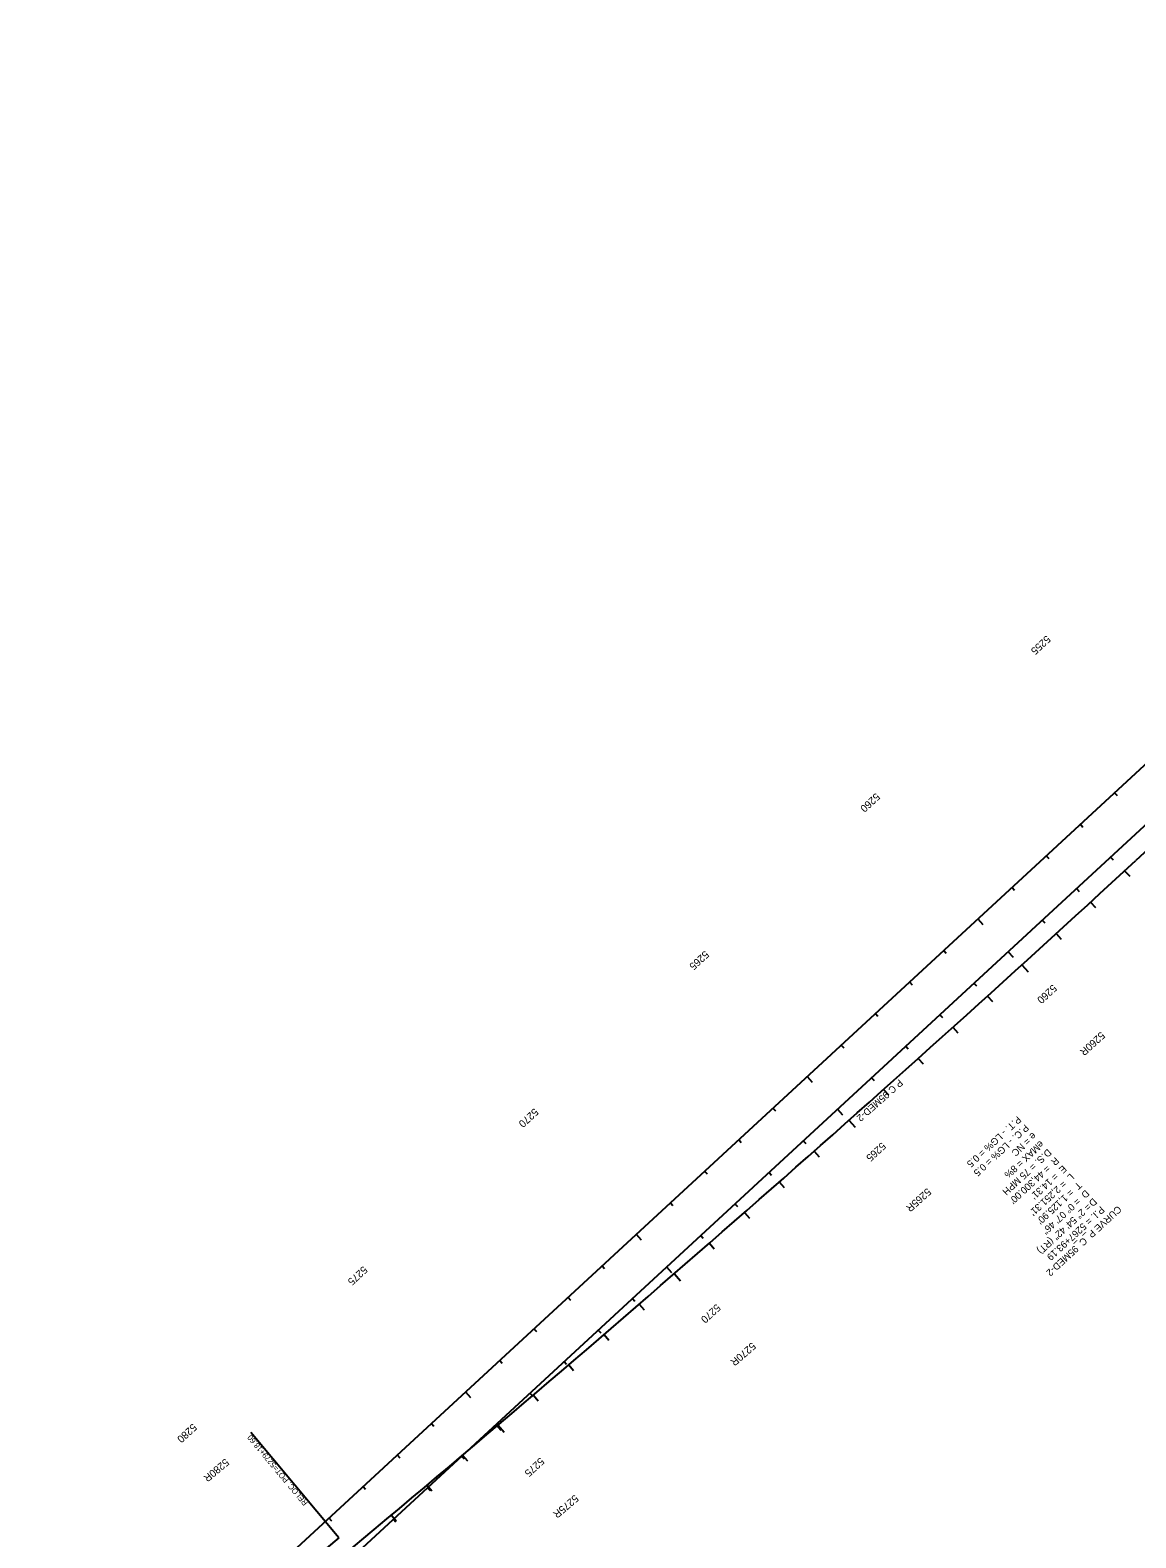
# Model space of a CAD drawing. Extents: x 2160877 to 2175861, y 601747 to 617724.
# Drawn here: x 2163672 to 2166050, y 606444 to 609688 of the extents above; entities that cross this region are included whole.
import ezdxf

# ---------------------------------------------------------------- set-up
doc = ezdxf.new("R2010")
doc.units = 0
for name, color, linetype in [('RD_HC_Cl', 7, 'Continuous'), ('RD_HC_CL_Rel', 7, 'Continuous'), ('RD_HC_Data_Rel', 7, 'Continuous'), ('RD_HC_Data_Tic', 7, 'Continuous'), ('RD_HC_Data_Tic_Rel', 7, 'Continuous'), ('RD_HC_TX_Rel_Sta50', 7, 'Continuous'), ('RD_HC_TX_StaOther', 7, 'Continuous')]:
    doc.layers.add(name, color=color, linetype=linetype)

msp = doc.modelspace()

# ---------------------------------------------------------------- linework, layer by layer
at = {"layer": 'RD_HC_Cl'}
for p, q in [((2172207.3, 613775.1), (2163672.2, 605893.8)), ((2172272.5, 613704.6), (2163737.4, 605823.3))]:
    msp.add_line(p, q, dxfattribs=at)
at = {"layer": 'RD_HC_CL_Rel'}
for p, q in [((2167327.7, 609081.4), (2166050.4, 607902)), ((2164335.8, 606444.4), (2163946.7, 606120.1))]:
    msp.add_line(p, q, dxfattribs=at)
msp.add_arc((2135996.9, 640448.5), 44300, 309.80773, 312.71947, dxfattribs=at)
at = {"layer": 'RD_HC_Data_Rel'}
msp.add_line((2164335.8, 606444.4), (2164147.1, 606670.9), dxfattribs=at)
at = {"layer": 'RD_HC_Data_Tic'}
for p, q in [((2166004.5, 608047.5), (2166010, 608041.6)), ((2165931.1, 607979.6), (2165936.5, 607973.7)), ((2165857.6, 607911.8), (2165863, 607905.9)), ((2165996.2, 607909.1), (2166001.6, 607903.2)), ((2165784.1, 607843.9), (2165789.6, 607838.1)), ((2165922.7, 607841.3), (2165928.2, 607835.4)), ((2165710.7, 607776.1), (2165721.5, 607764.3)), ((2165849.3, 607773.4), (2165854.7, 607767.5)), ((2165637.2, 607708.3), (2165642.6, 607702.4)), ((2165775.8, 607705.6), (2165786.6, 607693.8)), ((2165563.7, 607640.4), (2165569.2, 607634.5)), ((2165702.3, 607637.7), (2165707.7, 607631.9)), ((2165490.3, 607572.6), (2165495.7, 607566.7)), ((2165628.9, 607569.9), (2165634.3, 607564)), ((2165416.8, 607504.7), (2165422.2, 607498.9)), ((2165555.4, 607502.1), (2165560.8, 607496.2)), ((2165343.3, 607436.9), (2165354.2, 607425.1)), ((2165481.9, 607434.2), (2165487.3, 607428.3)), ((2165269.8, 607369.1), (2165275.3, 607363.2)), ((2165408.4, 607366.4), (2165419.3, 607354.6)), ((2165196.4, 607301.2), (2165201.8, 607295.3)), ((2165335, 607298.5), (2165340.4, 607292.7)), ((2165122.9, 607233.4), (2165128.3, 607227.5)), ((2165261.5, 607230.7), (2165266.9, 607224.8)), ((2165049.4, 607165.5), (2165054.9, 607159.7)), ((2165188, 607162.8), (2165193.5, 607157)), ((2164976, 607097.7), (2164986.8, 607085.9)), ((2165114.6, 607095), (2165120, 607089.1)), ((2164902.5, 607029.9), (2164907.9, 607024)), ((2165041.1, 607027.2), (2165052, 607015.4)), ((2164829, 606962), (2164834.5, 606956.1)), ((2164967.6, 606959.3), (2164973.1, 606953.4)), ((2164755.6, 606894.2), (2164761, 606888.3)), ((2164894.2, 606891.5), (2164899.6, 606885.6)), ((2164682.1, 606826.3), (2164687.5, 606820.5)), ((2164820.7, 606823.6), (2164826.1, 606817.8)), ((2164608.6, 606758.5), (2164619.5, 606746.7)), ((2164747.2, 606755.8), (2164752.7, 606749.9)), ((2164535.2, 606690.6), (2164540.6, 606684.8)), ((2164673.8, 606688), (2164684.6, 606676.2)), ((2164461.7, 606622.8), (2164467.1, 606616.9)), ((2164600.3, 606620.1), (2164605.7, 606614.2)), ((2164388.2, 606555), (2164393.7, 606549.1)), ((2164526.8, 606552.3), (2164532.3, 606546.4)), ((2164314.8, 606487.1), (2164320.2, 606481.2)), ((2164453.4, 606484.4), (2164458.8, 606478.6))]:
    msp.add_line(p, q, dxfattribs=at)
at = {"layer": 'RD_HC_Data_Tic_Rel'}
for p, q in [((2166026.4, 607879.8), (2166037.2, 607868.1)), ((2165952.8, 607812.1), (2165963.6, 607800.3)), ((2165879, 607744.6), (2165889.8, 607732.8)), ((2165805.1, 607677.2), (2165818.6, 607662.4)), ((2165731.1, 607610), (2165741.8, 607598.2)), ((2165656.9, 607543), (2165667.6, 607531.1)), ((2165582.5, 607476.1), (2165593.2, 607464.2)), ((2165508, 607409.4), (2165518.7, 607397.5)), ((2165433.4, 607342.9), (2165446.7, 607327.9)), ((2165358.6, 607276.5), (2165369.2, 607264.5)), ((2165283.6, 607210.3), (2165294.2, 607198.3)), ((2165208.5, 607144.3), (2165219.1, 607132.3)), ((2165133.3, 607078.4), (2165143.8, 607066.4)), ((2165057.9, 607012.8), (2165071, 606997.7)), ((2164982.3, 606947.2), (2164992.8, 606935.1)), ((2164906.6, 606881.9), (2164917.1, 606869.8)), ((2164830.8, 606816.7), (2164841.2, 606804.6)), ((2164754.8, 606751.7), (2164765.2, 606739.5)), ((2164678.6, 606686.9), (2164691.6, 606671.6)), ((2164602.4, 606622.2), (2164612.7, 606610)), ((2164525.9, 606557.7), (2164536.2, 606545.5)), ((2164449.3, 606493.4), (2164459.6, 606481.2))]:
    msp.add_line(p, q, dxfattribs=at)

# ---------------------------------------------------------------- texts
at = {"layer": 'RD_HC_Data_Rel'}
for s, height, rotation, p in [('P C 95MED-2', 15, 221.4251, (2165541.4, 607432)), ('P.T. - LG% = 0.5', 15, 222.7195, (2165795.6, 607352.8)), ('P.C. - LG% = 0.5', 15, 222.7195, (2165811.9, 607335.2)), ('e = NC', 15, 222.7195, (2165828.1, 607317.6)), ('D.S. = 75 MPH', 15, 222.7195, (2165860.7, 607282.3)), ('eMAX = 8%', 15, 222.7195, (2165844.4, 607299.9)), ("R  = 44,300.00'", 15, 222.7195, (2165877, 607264.7)), ("E  = 14.31'", 15, 222.7195, (2165893.3, 607247.1)), ("L  = 2,251.31'", 15, 222.7195, (2165909.6, 607229.4)), ("T  = 1,125.90'", 15, 222.7195, (2165925.8, 607211.8)), ('D  = 0%%d 07\' 46"', 15, 222.7195, (2165942.1, 607194.2)), ('D ', 15, 222.7195, (2165958.4, 607176.5)), ('   = 2%%d 54\' 42" (RT)', 15, 222.7195, (2165958.4, 607176.5)), ('CURVE P_C_95MED-2', 15, 222.7195, (2166011.3, 607160)), ('P.I. = 5267+93.19', 15, 222.7195, (2165974.7, 607158.9)), ('RELOC. POT=5279+18.60', 12, 129.8077, (2164270.3, 606519.9))]:
    msp.add_text(s, height=height, rotation=rotation, dxfattribs=at).set_placement(p)
at = {"layer": 'RD_HC_TX_Rel_Sta50'}
for s, rotation, p in [('5260R', 222.2892, (2165975.2, 607534.5)), ('5265R', 221.6425, (2165601.6, 607198)), ('5270R', 220.9958, (2165224.6, 606866.2)), ('5280R', 219.8077, (2164091.9, 606616)), ('5275R', 220.3491, (2164843.5, 606538.3))]:
    msp.add_text(s, height=16, rotation=rotation, dxfattribs=at).set_placement(p)
at = {"layer": 'RD_HC_TX_StaOther'}
for s, p in [('5255', (2165858.1, 608387.1)), ('5260', (2165491.2, 608048.2)), ('5265', (2165123.5, 607708.7)), ('5260', (2165871.6, 607636.2)), ('5270', (2164756.5, 607369.8)), ('5265', (2165503.9, 607296.6)), ('5275', (2164388.8, 607030.3)), ('5270', (2165148.3, 606948.8)), ('5280', (2164021.8, 606691.4)), ('5275', (2164769.2, 606618.2))]:
    msp.add_text(s, height=16, rotation=222.7195, dxfattribs=at).set_placement(p)

doc.saveas('drawing.dxf')
